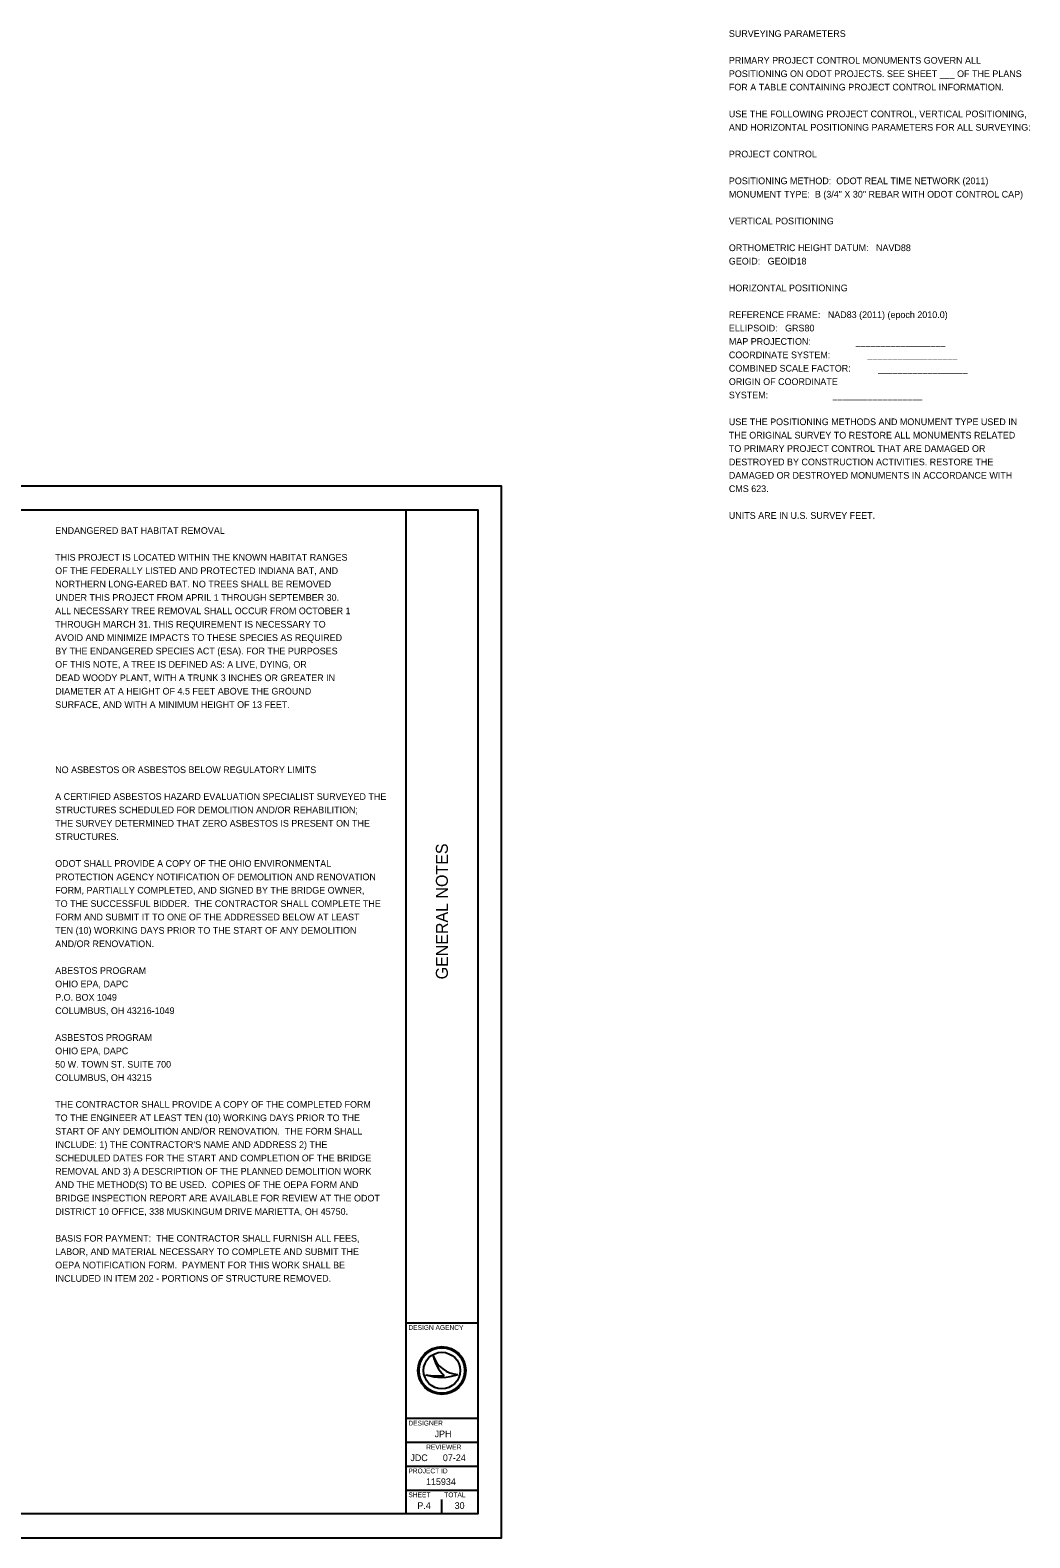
# Model space of a CAD drawing. Extents: x -32.1 to 45.1, y 0 to 43.7.
# Drawn here: x 24.14 to 45.05, y 0 to 31.54 of the extents above; entities that cross this region are included whole.
import ezdxf

# ---------------------------------------------------------------- set-up
doc = ezdxf.new("R2010")
doc.units = 0
for name, color, linetype in [('SH_Border', 7, 'Continuous'), ('SH_Cut_Line', 7, 'Continuous'), ('SH_Data', 7, 'Continuous'), ('SH_Text', 7, 'Continuous')]:
    doc.layers.add(name, color=color, linetype=linetype)

msp = doc.modelspace()

# ---------------------------------------------------------------- linework, layer by layer
at = {"layer": 'SH_Border'}
for p, q in [((32, 0.5), (32, 21.5)), ((32, 4.5), (33.5, 4.5)), ((32, 2.5), (33.5, 2.5)), ((32, 2), (33.5, 2)), ((32, 1.5), (33.5, 1.5)), ((32, 1), (33.5, 1))]:
    msp.add_line(p, q, dxfattribs=at)
msp.add_lwpolyline([(1.5, 21.5), (33.5, 21.5), (33.5, 0.5), (1.5, 0.5)], close=True, dxfattribs=at)
at = {"layer": 'SH_Cut_Line'}
msp.add_lwpolyline([(0, 0), (34, 0), (34, 22), (0, 22)], close=True, dxfattribs=at)
at = {"layer": 'SH_Data'}
for p, q in [((32.567, 3.81), (32.567, 3.81)), ((32.75, 3.5), (32.75, 3.5)), ((32.417, 3.41), (32.417, 3.41)), ((33.087, 3.419), (33.087, 3.419)), ((32.375, 0.675), (32.375, 0.675)), ((32.75, 0.5), (32.75, 0.8))]:
    msp.add_line(p, q, dxfattribs=at)
for radius in [0.5, 0.477, 0.477, 0.382]:
    msp.add_circle((32.75, 3.5), radius, dxfattribs=at)
for centre, radius, start, end in [((33.116, 3.998), 0.58, 198.9257, 198.9319), ((33.347, 3.97), 0.796, 191.6379, 191.6421), ((33.116, 3.998), 0.58, 198.9319, 267.1657), ((33.347, 3.97), 0.796, 191.6421, 226.0947), ((32.739, 4.37), 1.013, 251.4576, 290.0832), ((32.648, 4.654), 1.266, 259.4964, 259.4995), ((32.739, 4.37), 1.013, 251.4527, 251.4576), ((32.648, 4.654), 1.266, 259.4995, 276.6672)]:
    msp.add_arc(centre, radius, start, end, dxfattribs=at)

# ---------------------------------------------------------------- texts
msp.add_text('GENERAL NOTES', height=0.25, rotation=90, dxfattribs=at).set_placement((32.875, 11.682))
for s, height, p in [('DESIGN AGENCY', 0.1, (32.05, 4.35)), ('DESIGNER', 0.1, (32.05, 2.35)), ('JPH', 0.14, (32.598, 2.105)), ('REVIEWER', 0.1, (32.422, 1.85)), ('JDC', 0.14, (32.091, 1.605)), ('07-24', 0.14, (32.771, 1.605)), ('PROJECT ID', 0.1, (32.05, 1.35)), ('SHEET', 0.1, (32.05, 0.85)), ('115934', 0.14, (32.418, 1.105)), ('TOTAL', 0.1, (32.8, 0.85)), ('P.4', 0.14, (32.237, 0.605)), ('30', 0.14, (33.017, 0.605))]:
    msp.add_text(s, height=height, dxfattribs=at).set_placement(p)
at = {"layer": 'SH_Text'}
for s, p in [('SURVEYING PARAMETERS', (38.755, 31.395)), ('PRIMARY PROJECT CONTROL MONUMENTS GOVERN ALL', (38.755, 30.835)), ('POSITIONING ON ODOT PROJECTS. SEE SHEET ___ OF THE PLANS', (38.755, 30.555)), ('FOR A TABLE CONTAINING PROJECT CONTROL INFORMATION.', (38.755, 30.275)), ('USE THE FOLLOWING PROJECT CONTROL, VERTICAL POSITIONING,', (38.755, 29.715)), ('AND HORIZONTAL POSITIONING PARAMETERS FOR ALL SURVEYING:', (38.755, 29.435)), ('PROJECT CONTROL', (38.755, 28.875)), ('POSITIONING METHOD:  ODOT REAL TIME NETWORK (2011)', (38.755, 28.315)), ('MONUMENT TYPE:  B (3/4" X 30" REBAR WITH ODOT CONTROL CAP)', (38.755, 28.035)), ('VERTICAL POSITIONING', (38.755, 27.475)), ('ORTHOMETRIC HEIGHT DATUM:   NAVD88', (38.755, 26.915)), ('GEOID:   GEOID18', (38.755, 26.635)), ('HORIZONTAL POSITIONING', (38.755, 26.075)), ('REFERENCE FRAME:   NAD83 (2011) (epoch 2010.0)', (38.755, 25.515)), ('ELLIPSOID:   GRS80', (38.755, 25.235)), ('MAP PROJECTION:                  __________________', (38.755, 24.955)), ('COORDINATE SYSTEM:               __________________', (38.755, 24.675)), ('COMBINED SCALE FACTOR:           __________________', (38.755, 24.395)), ('ORIGIN OF COORDINATE', (38.755, 24.115)), ('SYSTEM:                          __________________', (38.755, 23.835)), ('USE THE POSITIONING METHODS AND MONUMENT TYPE USED IN', (38.755, 23.275)), ('THE ORIGINAL SURVEY TO RESTORE ALL MONUMENTS RELATED', (38.755, 22.995)), ('TO PRIMARY PROJECT CONTROL THAT ARE DAMAGED OR', (38.755, 22.715)), ('DESTROYED BY CONSTRUCTION ACTIVITIES. RESTORE THE', (38.755, 22.435)), ('DAMAGED OR DESTROYED MONUMENTS IN ACCORDANCE WITH', (38.755, 22.155)), ('CMS 623.', (38.755, 21.875)), ('UNITS ARE IN U.S. SURVEY FEET.', (38.755, 21.315)), ('ENDANGERED BAT HABITAT REMOVAL', (24.66, 21)), ('THIS PROJECT IS LOCATED WITHIN THE KNOWN HABITAT RANGES', (24.66, 20.44)), ('OF THE FEDERALLY LISTED AND PROTECTED INDIANA BAT, AND', (24.66, 20.16)), ('NORTHERN LONG-EARED BAT. NO TREES SHALL BE REMOVED', (24.66, 19.88)), ('UNDER THIS PROJECT FROM APRIL 1 THROUGH SEPTEMBER 30.', (24.66, 19.6)), ('ALL NECESSARY TREE REMOVAL SHALL OCCUR FROM OCTOBER 1', (24.66, 19.32)), ('THROUGH MARCH 31. THIS REQUIREMENT IS NECESSARY TO', (24.66, 19.04)), ('AVOID AND MINIMIZE IMPACTS TO THESE SPECIES AS REQUIRED', (24.66, 18.76)), ('BY THE ENDANGERED SPECIES ACT (ESA). FOR THE PURPOSES', (24.66, 18.48)), ('OF THIS NOTE, A TREE IS DEFINED AS: A LIVE, DYING, OR', (24.66, 18.2)), ('DEAD WOODY PLANT, WITH A TRUNK 3 INCHES OR GREATER IN', (24.66, 17.92)), ('DIAMETER AT A HEIGHT OF 4.5 FEET ABOVE THE GROUND', (24.66, 17.64)), ('SURFACE, AND WITH A MINIMUM HEIGHT OF 13 FEET.', (24.66, 17.36)), ('NO ASBESTOS OR ASBESTOS BELOW REGULATORY LIMITS', (24.66, 15.996)), ('A CERTIFIED ASBESTOS HAZARD EVALUATION SPECIALIST SURVEYED THE', (24.66, 15.436)), ('STRUCTURES SCHEDULED FOR DEMOLITION AND/OR REHABILITION;', (24.66, 15.156)), ('THE SURVEY DETERMINED THAT ZERO ASBESTOS IS PRESENT ON THE', (24.66, 14.876)), ('STRUCTURES.', (24.66, 14.596)), ('ODOT SHALL PROVIDE A COPY OF THE OHIO ENVIRONMENTAL', (24.66, 14.036)), ('PROTECTION AGENCY NOTIFICATION OF DEMOLITION AND RENOVATION', (24.66, 13.756)), ('FORM, PARTIALLY COMPLETED, AND SIGNED BY THE BRIDGE OWNER,', (24.66, 13.476)), ('TO THE SUCCESSFUL BIDDER.  THE CONTRACTOR SHALL COMPLETE THE', (24.66, 13.196)), ('FORM AND SUBMIT IT TO ONE OF THE ADDRESSED BELOW AT LEAST', (24.66, 12.916)), ('TEN (10) WORKING DAYS PRIOR TO THE START OF ANY DEMOLITION', (24.66, 12.636)), ('AND/OR RENOVATION.', (24.66, 12.356)), ('ABESTOS PROGRAM', (24.66, 11.796)), ('OHIO EPA, DAPC', (24.66, 11.516)), ('P.O. BOX 1049', (24.66, 11.236)), ('COLUMBUS, OH 43216-1049', (24.66, 10.956)), ('ASBESTOS PROGRAM', (24.66, 10.396)), ('OHIO EPA, DAPC', (24.66, 10.116)), ('50 W. TOWN ST. SUITE 700', (24.66, 9.836)), ('COLUMBUS, OH 43215', (24.66, 9.556)), ('THE CONTRACTOR SHALL PROVIDE A COPY OF THE COMPLETED FORM', (24.66, 8.996)), ('TO THE ENGINEER AT LEAST TEN (10) WORKING DAYS PRIOR TO THE', (24.66, 8.716)), ('START OF ANY DEMOLITION AND/OR RENOVATION.  THE FORM SHALL', (24.66, 8.436)), ("INCLUDE: 1) THE CONTRACTOR'S NAME AND ADDRESS 2) THE", (24.66, 8.156)), ('SCHEDULED DATES FOR THE START AND COMPLETION OF THE BRIDGE', (24.66, 7.876)), ('REMOVAL AND 3) A DESCRIPTION OF THE PLANNED DEMOLITION WORK', (24.66, 7.596)), ('AND THE METHOD(S) TO BE USED.  COPIES OF THE OEPA FORM AND', (24.66, 7.316)), ('BRIDGE INSPECTION REPORT ARE AVAILABLE FOR REVIEW AT THE ODOT ', (24.66, 7.036)), ('DISTRICT 10 OFFICE, 338 MUSKINGUM DRIVE MARIETTA, OH 45750.', (24.66, 6.756)), ('BASIS FOR PAYMENT:  THE CONTRACTOR SHALL FURNISH ALL FEES,', (24.66, 6.196)), ('LABOR, AND MATERIAL NECESSARY TO COMPLETE AND SUBMIT THE', (24.66, 5.916)), ('OEPA NOTIFICATION FORM.  PAYMENT FOR THIS WORK SHALL BE', (24.66, 5.636)), ('INCLUDED IN ITEM 202 - PORTIONS OF STRUCTURE REMOVED.', (24.66, 5.356))]:
    msp.add_text(s, height=0.14, dxfattribs=at).set_placement(p)

doc.saveas('drawing.dxf')
